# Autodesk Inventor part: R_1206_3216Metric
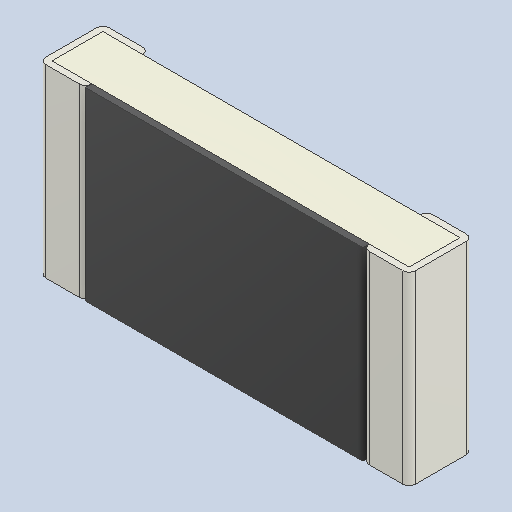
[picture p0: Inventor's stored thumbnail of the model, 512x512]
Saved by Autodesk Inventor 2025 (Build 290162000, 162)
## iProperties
Created: 2026-09
Part Number: R_1206_3216Metric
Material: Generic
Document SubType Name: Modeling
Designer: Leonardo
Density: 1 g/cm^3
Appearance: Default
Author: Leonardo
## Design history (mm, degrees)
feature "Base1"
body "Solid1"
